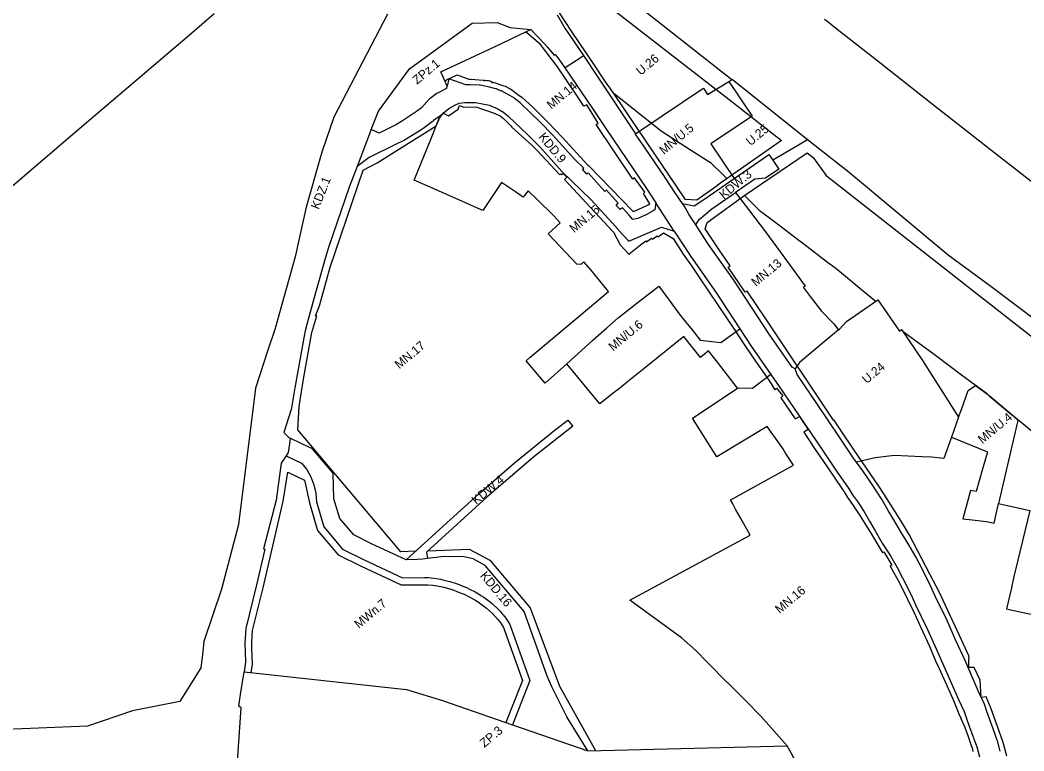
# Model space of a CAD drawing. Extents: x 7418616 to 7420822, y 5550745 to 5553106.
# Drawn here: x 7419553 to 7420122, y 5552455 to 5552869 of the extents above; entities that cross this region are included whole.
import ezdxf

# ---------------------------------------------------------------- set-up
doc = ezdxf.new("R2010")
doc.units = 0
for name, color, linetype in [('granica obszaru objętego planem', 7, 'Continuous'), ('granica strefy zwiększonej wysokości zabudowy', 7, 'Continuous'), ('linie rozgraniczające', 7, 'Continuous'), ('nieprzekraczalne linie zabudowy', 7, 'Continuous'), ('przeznaczenia terenów', 7, 'Continuous')]:
    doc.layers.add(name, color=color, linetype=linetype)

msp = doc.modelspace()

# ---------------------------------------------------------------- linework, layer by layer
at = {"layer": 'granica obszaru objętego planem'}
for points in [[(7419511.19, 5552742.76), (7419587.29, 5552807.63), (7419649.27, 5552860.47), (7419663.39, 5552872.55)], [(7420009.05, 5552869.32), (7420011.09, 5552867.73), (7420013.23, 5552866.06), (7420016.26, 5552863.7), (7420037.45, 5552847.04), (7420069.08, 5552822.2), (7420100.3, 5552797.65), (7420126.01, 5552777.58)]]:
    msp.add_lwpolyline(points, dxfattribs=at)
at = {"layer": 'granica strefy zwiększonej wysokości zabudowy'}
for points in [[(7419953.76, 5552779.05), (7419951.41, 5552781.34), (7419945.01, 5552787.57), (7419933.17, 5552795.21), (7419916.46, 5552805.97), (7419900.76, 5552818.37), (7419889.84, 5552826.97)], [(7420037.9, 5552709.57), (7420037.54, 5552709.87), (7420030.83, 5552715.39), (7420028.98, 5552716.91), (7420025.2, 5552720.02), (7420015.41, 5552728.06), (7420010.79, 5552731.63), (7419996.62, 5552742.4), (7419993.7, 5552744.61), (7419983.14, 5552752.63), (7419975.57, 5552758.38), (7419972.82, 5552760.47), (7419966.67, 5552766.47), (7419963.6, 5552769.46), (7419963.6, 5552769.46)], [(7420128.4, 5552634.31), (7420121.47, 5552639.97), (7420116.2, 5552644.3), (7420115.06, 5552645.24), (7420102.17, 5552656.1), (7420101.24, 5552656.92), (7420100.49, 5552657.47), (7420096.92, 5552660.13), (7420087.43, 5552667.21), (7420071.86, 5552678.81), (7420059.99, 5552687.55), (7420054.92, 5552691.27), (7420053.6, 5552692.24)]]:
    msp.add_lwpolyline(points, dxfattribs=at)
at = {"layer": 'linie rozgraniczające'}
for p, q in [((7419956.54, 5552835), (7419872.88, 5552900.79)), ((7419954.88, 5552833.99), (7419956.54, 5552835)), ((7419752.34, 5552806.9), (7419744.23, 5552785.82)), ((7419923.94, 5552749.19), (7419913.47, 5552765.28)), ((7420084.95, 5552643.93), (7420080.88, 5552632.69)), ((7420107.63, 5552595.09), (7420125.31, 5552591.19)), ((7419832.38, 5552469.77), (7419874.87, 5552455.06)), ((7419874.87, 5552455.06), (7419987.78, 5552457.79))]:
    msp.add_line(p, q, dxfattribs=at)
for points in [[(7419511.19, 5552742.76), (7419587.29, 5552807.63), (7419649.27, 5552860.47), (7419663.39, 5552872.55)], [(7419761.46, 5552872.12), (7419731.19, 5552813.82), (7419724.58, 5552794.59), (7419723.5, 5552791.44), (7419715.5, 5552762.81), (7419712.67, 5552750.3), (7419709.62, 5552736.46), (7419709.14, 5552734.73), (7419698.05, 5552694.95), (7419697.83, 5552694.15), (7419693.59, 5552681.37), (7419686.69, 5552660.34), (7419677.11, 5552583.24), (7419667.39, 5552546.6), (7419657.52, 5552516.96), (7419656.86, 5552511.21), (7419655.81, 5552502.07), (7419643.8, 5552483.02), (7419617.1, 5552477.61), (7419591.51, 5552469.04), (7419508.13, 5552465.61)], [(7419752.34, 5552806.9), (7419756.31, 5552817.21), (7419773.92, 5552841.15), (7419809.49, 5552867.01), (7419823.66, 5552867.37), (7419831.02, 5552864.55), (7419842.51, 5552863.51), (7419842.62, 5552863.41)], [(7419857.66, 5552871.76), (7419861.98, 5552864.31), (7419872.48, 5552848.66)], [(7420009.05, 5552869.32), (7420011.09, 5552867.73), (7420013.23, 5552866.06), (7420016.26, 5552863.7), (7420037.45, 5552847.04), (7420069.08, 5552822.2), (7420100.3, 5552797.65), (7420126.01, 5552777.58)], [(7419795.2, 5552831.44), (7419793.94, 5552834.32), (7419791.76, 5552839.51), (7419822.43, 5552853.79), (7419840.21, 5552862.41), (7419842.62, 5552863.41)], [(7419842.62, 5552863.41), (7419843.74, 5552862.28), (7419845.58, 5552860.39), (7419846.51, 5552859.44), (7419850.32, 5552855.63), (7419850.51, 5552855.38), (7419851.85, 5552853.63), (7419855.85, 5552848.96), (7419856.43, 5552849.35), (7419858.53, 5552846.61), (7419861.9, 5552841.73)], [(7419861.9, 5552841.73), (7419862.14, 5552841.89), (7419871.71, 5552848.2), (7419872.48, 5552848.66)], [(7419872.48, 5552848.66), (7419880.27, 5552837.04), (7419902.02, 5552804.48)], [(7419861.9, 5552841.73), (7419877.6, 5552818.69), (7419885.52, 5552806.89), (7419908.16, 5552773.44), (7419913.47, 5552765.28)], [(7419913.47, 5552765.28), (7419912.82, 5552761.39), (7419911.94, 5552760.8), (7419907.55, 5552758.32), (7419907.47, 5552758.32), (7419903.34, 5552756.4), (7419900.37, 5552755.91), (7419899.25, 5552757.18), (7419898.31, 5552758.38), (7419894.65, 5552762.4), (7419893.18, 5552761.51), (7419891, 5552763.9), (7419892.21, 5552765.08), (7419885.49, 5552772.46), (7419884.56, 5552771.74), (7419875.1, 5552782.25), (7419874.43, 5552781.61), (7419871.98, 5552784.45), (7419872.67, 5552785.04), (7419867.6, 5552789.93), (7419855.21, 5552803.56), (7419847.93, 5552810.98), (7419836.74, 5552821.75), (7419836.57, 5552821.91), (7419833.28, 5552824.64), (7419832.87, 5552824.94), (7419832.56, 5552825.13), (7419828.41, 5552827.48), (7419828, 5552827.69), (7419827.27, 5552828.02), (7419826.32, 5552828.9), (7419825.94, 5552828.62), (7419823.58, 5552829.68), (7419823.27, 5552829.8), (7419822.93, 5552829.9), (7419818.44, 5552831.08), (7419813.89, 5552831.96), (7419813.56, 5552831.99), (7419808.26, 5552832.21), (7419805.77, 5552832.21), (7419796.21, 5552835.55), (7419795.2, 5552831.44)], [(7419902.02, 5552804.48), (7419905.45, 5552806.79), (7419928.51, 5552822.26), (7419928.75, 5552822.42), (7419940.43, 5552830.25), (7419940.73, 5552829.82), (7419942.71, 5552826.63), (7419942.82, 5552826.74), (7419954.16, 5552833.56), (7419954.88, 5552833.99)], [(7419954.88, 5552833.99), (7419967.94, 5552814.48), (7419944.56, 5552798.82), (7419957.81, 5552779.08)], [(7419999.41, 5552800.99), (7419956.78, 5552835.14), (7419956.54, 5552835)], [(7419795.2, 5552831.44), (7419795.18, 5552831.35), (7419794.87, 5552830.07), (7419790.15, 5552827.65), (7419789.66, 5552827.36), (7419785.59, 5552824.4), (7419785.34, 5552824.19), (7419785.1, 5552823.97), (7419782.25, 5552820.9), (7419780.67, 5552819.08), (7419777.87, 5552817), (7419775.74, 5552815.45), (7419772.83, 5552813.6), (7419769.34, 5552811.35), (7419766.14, 5552809.42), (7419761.71, 5552807.24), (7419756.72, 5552804.83), (7419752.34, 5552806.9)], [(7419791.06, 5552814.47), (7419793.1, 5552816.02), (7419796.27, 5552818.73), (7419799.6, 5552820.66), (7419802.06, 5552821.75), (7419805.23, 5552822.21), (7419808.16, 5552822.21), (7419811.25, 5552822.08), (7419819.2, 5552820.54), (7419819.99, 5552820.33), (7419823.68, 5552818.67), (7419827.24, 5552816.65), (7419829.93, 5552814.42), (7419840.94, 5552803.82), (7419847.87, 5552796.76), (7419860.31, 5552783.08), (7419876.93, 5552767), (7419890.72, 5552751.86), (7419892.05, 5552750.14), (7419892.24, 5552749.92), (7419898.27, 5552743.61), (7419916.6, 5552751.5), (7419923.94, 5552749.19)], [(7419791.06, 5552814.47), (7419787.61, 5552811.86), (7419787.38, 5552811.63), (7419787.06, 5552811.38), (7419783.82, 5552808.96), (7419781.49, 5552807.27), (7419774.56, 5552802.81), (7419771.11, 5552800.74), (7419770.74, 5552800.54), (7419766.11, 5552798.26), (7419751.2, 5552791.07), (7419744.23, 5552785.82)], [(7419863.01, 5552674.16), (7419850.8, 5552663.17), (7419840.04, 5552675.92), (7419842.35, 5552677.85), (7419870.05, 5552701.17), (7419875.9, 5552706.11), (7419886.58, 5552715.12), (7419876.81, 5552727.26), (7419872.68, 5552731.87), (7419870.91, 5552730.48), (7419868.69, 5552730.64), (7419852.44, 5552747.72), (7419859.26, 5552754.09), (7419855.53, 5552758.1), (7419846.1, 5552767.33), (7419841.15, 5552772.14), (7419838.29, 5552768.62), (7419837.21, 5552769.35), (7419834.49, 5552771.18), (7419826.13, 5552776.8), (7419815.51, 5552761.02), (7419793.79, 5552770.54), (7419776.59, 5552778.12), (7419786.22, 5552801.72), (7419789.12, 5552808.86), (7419790.54, 5552812.34), (7419791.06, 5552814.47)], [(7419928.52, 5552764.94), (7419924.86, 5552770.37), (7419924.69, 5552770.63), (7419918.96, 5552779.21), (7419918.36, 5552780.14), (7419904.66, 5552800.36), (7419904.44, 5552800.69), (7419902.02, 5552804.28), (7419902.02, 5552804.48)], [(7419999.41, 5552800.99), (7419990.99, 5552796.02), (7419979.75, 5552789.39)], [(7420315.68, 5552545.3), (7420299.67, 5552559.37), (7420293.91, 5552563.84), (7420282.98, 5552572.32), (7420270.37, 5552582.11), (7420259.31, 5552590.7), (7420247.5, 5552599.87), (7420235.93, 5552609.17), (7420223.99, 5552618.12), (7420216.53, 5552623.99), (7420206.96, 5552631.81), (7420203.16, 5552634.99), (7420193.46, 5552643.91), (7420178, 5552656.63), (7420165.36, 5552667.99), (7420163.22, 5552670.42), (7420147.94, 5552682.92), (7420134.85, 5552693.95), (7420132.47, 5552696.06), (7420130.02, 5552697.81), (7420103.9, 5552717.31), (7420079.03, 5552735.61), (7420022.01, 5552783.22), (7419999.41, 5552800.99)], [(7419957.81, 5552779.08), (7419974.77, 5552790.76), (7419977.5, 5552792.64), (7419979.75, 5552789.39)], [(7419979.75, 5552789.39), (7419983.18, 5552784.41), (7419975.62, 5552779.2), (7419969.57, 5552778.72), (7419958.66, 5552771.19)], [(7419744.23, 5552785.82), (7419739.76, 5552774.21), (7419728.04, 5552739.95), (7419726.22, 5552733.76), (7419719.78, 5552710.9), (7419716.51, 5552699.28), (7419714.79, 5552692.81), (7419714.1, 5552688.94), (7419709.02, 5552660.49), (7419707.12, 5552649.25), (7419706.86, 5552648.4), (7419702.84, 5552635.34), (7419705.9, 5552632.31), (7419706.42, 5552632.06)], [(7419928.52, 5552764.94), (7419935.25, 5552763.53), (7419941.2, 5552767.63), (7419957.81, 5552779.08)], [(7419936.14, 5552752.8), (7419938.08, 5552755.8), (7419945.13, 5552761.86), (7419958.66, 5552771.19)], [(7419958.66, 5552771.19), (7419966.58, 5552760.75), (7419975.51, 5552748.98), (7419991.62, 5552727), (7419998.13, 5552718.13), (7419996.9, 5552717.53), (7420001.46, 5552711.58), (7420007.33, 5552703.93), (7420014.37, 5552696.89), (7420016.09, 5552694.4), (7420016.98, 5552693.33)], [(7419936.14, 5552752.8), (7419932.38, 5552758.58), (7419929.83, 5552762.99), (7419928.52, 5552764.94)], [(7419923.94, 5552749.19), (7419933.25, 5552734.9), (7419947.46, 5552714.74), (7419961.09, 5552694.01)], [(7419992.43, 5552671.38), (7419990.65, 5552672.19), (7419977.68, 5552691), (7419957.58, 5552721.57), (7419943.37, 5552741.71), (7419936.14, 5552752.8)], [(7419863.01, 5552674.16), (7419877.79, 5552687.48), (7419885.66, 5552694.56), (7419892.06, 5552700.2), (7419902.76, 5552708.58), (7419915.09, 5552718.22), (7419927.75, 5552700.99), (7419933.96, 5552693.33), (7419938.54, 5552687.59), (7419950.37, 5552686.24), (7419961.09, 5552694.01)], [(7420016.98, 5552693.33), (7420017.48, 5552693.75), (7420021.47, 5552698.11), (7420039.21, 5552710.48), (7420051.42, 5552692.74), (7420052.7, 5552693.59), (7420064.45, 5552676.07), (7420084.95, 5552643.93)], [(7419961.09, 5552694.01), (7419967.54, 5552684.2), (7419978.67, 5552668.07)], [(7420016.98, 5552693.33), (7419994.89, 5552674.84), (7419992.43, 5552671.38)], [(7419959.77, 5552660.36), (7419948.4, 5552675.1), (7419946.91, 5552677.02), (7419943.37, 5552681.55), (7419938.73, 5552677.75), (7419929.28, 5552689.57), (7419908.8, 5552673.1), (7419897.49, 5552664.02), (7419893.06, 5552660.44), (7419888.59, 5552656.92), (7419881.83, 5552651.6), (7419863.01, 5552674.16)], [(7419978.67, 5552668.07), (7419968.17, 5552660.25), (7419959.77, 5552660.36)], [(7419978.67, 5552668.07), (7419983.35, 5552661.28), (7419994.62, 5552644.77), (7420007.78, 5552625.23), (7420015.83, 5552613.36), (7420020.78, 5552606.41), (7420022.57, 5552603.78), (7420024.88, 5552600.05), (7420027.78, 5552596.15), (7420031.3, 5552590.69), (7420034.43, 5552585.06), (7420037.75, 5552579.6), (7420041.73, 5552572.72), (7420046.3, 5552565.36), (7420050.16, 5552558.88), (7420053.22, 5552553.06), (7420058.01, 5552543.28), (7420060.68, 5552537.4), (7420067.3, 5552523.74), (7420072.16, 5552512.75), (7420077.43, 5552501.27), (7420084.92, 5552484.07), (7420088.11, 5552477.33), (7420089.39, 5552473.33), (7420090.89, 5552469.04), (7420093.06, 5552463.31), (7420095.28, 5552457.36), (7420096.79, 5552451.59)], [(7420027.16, 5552618.48), (7420025.88, 5552620.27), (7420022.11, 5552625.82), (7420017.89, 5552632.06), (7420004.71, 5552651.63), (7419994.22, 5552667.01), (7419993.51, 5552668.17), (7419992.43, 5552671.38)], [(7419987.78, 5552457.79), (7419972.94, 5552474.73), (7419964.07, 5552483.75), (7419954.62, 5552493.15), (7419954.14, 5552493.62), (7419942.69, 5552505), (7419936.15, 5552511.87), (7419928.09, 5552519.09), (7419898.8, 5552540.39), (7419966.87, 5552577.11), (7419961.4, 5552586.93), (7419958.85, 5552591.49), (7419957.01, 5552594.81), (7419955.72, 5552597.1), (7419957.3, 5552597.97), (7419991.39, 5552616.81), (7419986.94, 5552623.65), (7419985.32, 5552626.15), (7419983.64, 5552628.59), (7419978.83, 5552635.39), (7419976.53, 5552638.64), (7419947.99, 5552621.51), (7419934.31, 5552643.35), (7419956.12, 5552657.93), (7419959.77, 5552660.36)], [(7420084.95, 5552643.93), (7420086.75, 5552648.87), (7420090.46, 5552658.99), (7420094.45, 5552661.97), (7420101.24, 5552656.92), (7420102.17, 5552656.1), (7420115.06, 5552645.24), (7420118.58, 5552642.35), (7420118.33, 5552641.26), (7420107.63, 5552595.09)], [(7419772.1, 5552563.1), (7419792.99, 5552582.19), (7419812.95, 5552600.39), (7419833.39, 5552618.02), (7419856.71, 5552636.92), (7419863.6, 5552642.35), (7419866.12, 5552639.25), (7419866.44, 5552638.86), (7419844.3, 5552621.43), (7419817.72, 5552598.68), (7419783.54, 5552567.47), (7419784.21, 5552563.89)], [(7419706.42, 5552632.06), (7419705.98, 5552628.96), (7419705.28, 5552623.98), (7419705.17, 5552623.93), (7419704.03, 5552622.13)], [(7419772.1, 5552563.1), (7419752.46, 5552572.28), (7419742.35, 5552577.31), (7419734.47, 5552586.66), (7419731.16, 5552597.73), (7419730.7, 5552612.31), (7419718.93, 5552626.12), (7419712.63, 5552629.12), (7419706.42, 5552632.06)], [(7420080.88, 5552632.69), (7420076.5, 5552620.58), (7420069.55, 5552621.33), (7420064.05, 5552621.58), (7420048.73, 5552622.26), (7420037.72, 5552620.97), (7420027.16, 5552618.48)], [(7420080.88, 5552632.69), (7420101.29, 5552624.4), (7420101.13, 5552623.66), (7420098.37, 5552614.01), (7420094.92, 5552601.8), (7420091.78, 5552602.48), (7420087.38, 5552586.39), (7420092.68, 5552585.79), (7420100.71, 5552584.84), (7420105.04, 5552583.87), (7420107.63, 5552595.09)], [(7419704.03, 5552622.13), (7419701.36, 5552617.89), (7419698.38, 5552597.06), (7419691.29, 5552569.33), (7419691.97, 5552569.14), (7419687.37, 5552549.04), (7419681.18, 5552524.32), (7419680.61, 5552516.08), (7419681.02, 5552505.46), (7419680.88, 5552503.76), (7419680.25, 5552499.71)], [(7419704.03, 5552622.13), (7419712.7, 5552618.01), (7419715.72, 5552614.26), (7419718.13, 5552610.1), (7419719.87, 5552605.61), (7419720.9, 5552600.91), (7419721.21, 5552596.11), (7419725.48, 5552581.8), (7419736.04, 5552569.28), (7419748.36, 5552563.16), (7419770.06, 5552553.02), (7419782.5, 5552553.22), (7419784.7, 5552553.12), (7419786.2, 5552552.93), (7419787.7, 5552552.82), (7419789.12, 5552552.63), (7419790.31, 5552552.38), (7419791.54, 5552552.17), (7419792.83, 5552551.89), (7419794.29, 5552551.55), (7419795.81, 5552551.15), (7419796.91, 5552550.9), (7419797.99, 5552550.54), (7419799.43, 5552550.13), (7419801.04, 5552549.56), (7419802.05, 5552549.14), (7419804.11, 5552548.36), (7419805.38, 5552547.83), (7419806.58, 5552547.3), (7419808, 5552546.64), (7419811.09, 5552545.03), (7419813.06, 5552543.89), (7419814.41, 5552543.03), (7419816, 5552541.97), (7419817.63, 5552540.83), (7419819.09, 5552539.73), (7419820.75, 5552538.41), (7419821.89, 5552537.4), (7419823.71, 5552535.69), (7419824.73, 5552534.69), (7419825.49, 5552533.85), (7419826.32, 5552532.87), (7419827.08, 5552531.96), (7419828.54, 5552530.16), (7419829.92, 5552528.09), (7419830.8, 5552526.65), (7419842.15, 5552494.83), (7419832.38, 5552469.77)], [(7420108.57, 5552454.77), (7420107, 5552460.77), (7420106.87, 5552461.16), (7420104.48, 5552467.59), (7420102.39, 5552473.14), (7420100.95, 5552477.23), (7420099.6, 5552481.44), (7420099.43, 5552481.91), (7420096.07, 5552489.03), (7420088.59, 5552506.2), (7420083.27, 5552517.8), (7420078.42, 5552528.77), (7420071.69, 5552542.65), (7420069.08, 5552548.41), (7420064.13, 5552558.51), (7420060.77, 5552564.91), (7420056.7, 5552571.75), (7420052.14, 5552579.08), (7420048.21, 5552585.88), (7420044.99, 5552591.18), (7420041.87, 5552596.79), (7420041.66, 5552597.13), (7420035.26, 5552607.06), (7420030.62, 5552613.64), (7420027.16, 5552618.48)], [(7420125.31, 5552591.19), (7420118.51, 5552562.92), (7420116.31, 5552553.71), (7420114.85, 5552547.43), (7420112.01, 5552535.5), (7420116.32, 5552534.47), (7420123.3, 5552532.97), (7420130.59, 5552531.52), (7420140.63, 5552529.23), (7420148.9, 5552527.33)], [(7419784.21, 5552563.89), (7419781.46, 5552563.52), (7419778.26, 5552563.32), (7419772.1, 5552563.1)], [(7419874.87, 5552455.06), (7419863.09, 5552474.37), (7419858.95, 5552482.52), (7419854.66, 5552491.19), (7419851.86, 5552497.38), (7419838.84, 5552533.89), (7419816.86, 5552559.9), (7419809.96, 5552563.74), (7419804, 5552565.02), (7419791.88, 5552564.91), (7419784.21, 5552563.89)], [(7419676.51, 5552449.1), (7419678.57, 5552479.45), (7419677.27, 5552480.3), (7419678.28, 5552486.89), (7419680.25, 5552499.71)], [(7419680.25, 5552499.71), (7419772.19, 5552489.86), (7419792.7, 5552483.51), (7419832.38, 5552469.77)], [(7419998.25, 5552439.19), (7419998.18, 5552439.22), (7419987.78, 5552457.79)]]:
    msp.add_lwpolyline(points, dxfattribs=at)
at = {"layer": 'nieprzekraczalne linie zabudowy'}
for points in [[(7419854.22, 5552880.23), (7419862.41, 5552895.83), (7419956.75, 5552822.57), (7419984.73, 5552800.63), (7419948.25, 5552775.21), (7419948.2, 5552774.88), (7419936.75, 5552766.9), (7419930.27, 5552767.21), (7419890.06, 5552826.64), (7419887.27, 5552830.75), (7419886.32, 5552832), (7419884.57, 5552834.42), (7419884.67, 5552834.49), (7419877.92, 5552844.35), (7419866.03, 5552861.89), (7419854.22, 5552880.23)], [(7419793.97, 5552834.25), (7419794.93, 5552835.02), (7419800.97, 5552837.85), (7419807.65, 5552835.27), (7419808.04, 5552835.28), (7419808.22, 5552835.27), (7419808.24, 5552835.24), (7419808.29, 5552835.27), (7419808.44, 5552835.27), (7419815.95, 5552834.76), (7419816.23, 5552834.33), (7419816.82, 5552834.71), (7419818, 5552834.63), (7419818.64, 5552834.55), (7419819.55, 5552834.31), (7419820.29, 5552834.06), (7419820.8, 5552833.28), (7419821.42, 5552833.67), (7419827.32, 5552831.65), (7419828.1, 5552831.31), (7419831.34, 5552829.61), (7419831.86, 5552829.27), (7419835.36, 5552826.73), (7419837.8, 5552824.91), (7419843.58, 5552819.74), (7419852.17, 5552811.15), (7419852.55, 5552810.79), (7419860.47, 5552802.41), (7419874.95, 5552786.74), (7419875.48, 5552786.21), (7419900.38, 5552760.59), (7419900.72, 5552760.4), (7419901.84, 5552760.87), (7419905.95, 5552762.72), (7419909.18, 5552764.25), (7419910, 5552764.74), (7419906.47, 5552770.64), (7419907.17, 5552771.33), (7419901.48, 5552779.45), (7419900.54, 5552778.77), (7419879.74, 5552809.69), (7419880.73, 5552810.45), (7419874.31, 5552820.8), (7419872.75, 5552820.07), (7419869.79, 5552824.46), (7419869.41, 5552825), (7419861.81, 5552836.49), (7419857.69, 5552842.32), (7419848.06, 5552855.02), (7419840.39, 5552861.66), (7419838.94, 5552861.79)], [(7419777.47, 5552568.01), (7419769.08, 5552567.69), (7419710.71, 5552636.79), (7419711.49, 5552650.06), (7419713.96, 5552665.4), (7419718.69, 5552691.92), (7419721.46, 5552701.33), (7419720.65, 5552701.42), (7419722.9, 5552706.99), (7419729.01, 5552728.91), (7419747.81, 5552783.89), (7419755.62, 5552787.88), (7419789.15, 5552808.91), (7419790.63, 5552812.71), (7419793.1, 5552816.02), (7419796.13, 5552814.54), (7419801.57, 5552818.45), (7419802.33, 5552820.35), (7419804.67, 5552819.41), (7419804.89, 5552819.48), (7419811.46, 5552819.69), (7419821.92, 5552816.05), (7419825.4, 5552814.5), (7419827.26, 5552813.12), (7419831.28, 5552808.83), (7419831.87, 5552808.23), (7419843.42, 5552797.84), (7419846.26, 5552795.02), (7419859.15, 5552781.21), (7419859.63, 5552781.73), (7419860.28, 5552781.13), (7419860.99, 5552781.87), (7419863.09, 5552779.77), (7419861.73, 5552778.44), (7419889.06, 5552749.15), (7419889.53, 5552748.69), (7419893.33, 5552741.55), (7419898.25, 5552736.27), (7419904.72, 5552741.52), (7419907.82, 5552743.72), (7419908.16, 5552743.24), (7419911.05, 5552745.26), (7419911.52, 5552744.68), (7419914.32, 5552746.68), (7419914.74, 5552746.09), (7419917.83, 5552748.29), (7419923.29, 5552745.22), (7419929, 5552736.28), (7419930.92, 5552733.58), (7419933.64, 5552729.67), (7419938.12, 5552722.9), (7419953.46, 5552700.14), (7419958.21, 5552693.14), (7419962.31, 5552686.81), (7419968.16, 5552678.1), (7419977.76, 5552664.3), (7419980.94, 5552659.5), (7419981.86, 5552660.41), (7419985.33, 5552656.05), (7419984.2, 5552654.84), (7419992.3, 5552642.95), (7419994.88, 5552644.38), (7419999.84, 5552637.02), (7419997.29, 5552635.51), (7420003.42, 5552626.26), (7420010.07, 5552616.39), (7420019.15, 5552602.96), (7420019.75, 5552602.29), (7420019.67, 5552602.24), (7420019.85, 5552601.99), (7420020.08, 5552601.74), (7420022.12, 5552598.46), (7420024.87, 5552594.51), (7420029, 5552588.35), (7420036.25, 5552576.75), (7420041.66, 5552567.61), (7420041.85, 5552567.25), (7420042.52, 5552567.65), (7420047.06, 5552560.13), (7420046.2, 5552559.62), (7420051.71, 5552549.84), (7420060.17, 5552532.35), (7420063.52, 5552524.97), (7420068.25, 5552514.61), (7420071.96, 5552506.01), (7420073.94, 5552501.69), (7420081.63, 5552484.56), (7420085.43, 5552474.97), (7420086.31, 5552473.44), (7420086.14, 5552473.34), (7420088.22, 5552468.77), (7420090.13, 5552463.67), (7420092.08, 5552458.15), (7420092.55, 5552456.68), (7420093.03, 5552454.59)], [(7420112.21, 5552452.02), (7420110.18, 5552459.81), (7420110.04, 5552460.26), (7420107.07, 5552468.85), (7420103.41, 5552478.75), (7420100.6, 5552485.64), (7420097.82, 5552485.22), (7420097.11, 5552495.12), (7420093.79, 5552502.3), (7420090.78, 5552502.28), (7420090.75, 5552507.18), (7420090.85, 5552507.18), (7420090.79, 5552508.79), (7420085.44, 5552520.36), (7420076.24, 5552540.19), (7420074.07, 5552544.69), (7420068.7, 5552555), (7420056.89, 5552577.56), (7420052.4, 5552585.02), (7420044.28, 5552597.93), (7420040.16, 5552604.25), (7420025.49, 5552625.91), (7420018.48, 5552636.31), (7420014.3, 5552642.48), (7420014.11, 5552642.36), (7419997.07, 5552667.72), (7419997.17, 5552667.77), (7419992.84, 5552674.17), (7419990.91, 5552677.08), (7419975.72, 5552699.59), (7419965.17, 5552715.27), (7419964.06, 5552714.79), (7419954.42, 5552728.84), (7419955.5, 5552729.58), (7419949.29, 5552738.77), (7419941.41, 5552750.53), (7419942.49, 5552754.26), (7419963.23, 5552769.21), (7419999.26, 5552793.59), (7420002.64, 5552790.94), (7420009.96, 5552780.85), (7420097.4, 5552712.29), (7420192.63, 5552637.79)], [(7419684.23, 5552499.28), (7419684.99, 5552504.2), (7419684.72, 5552513.17), (7419684.66, 5552516.64), (7419685.12, 5552523.26), (7419686.53, 5552529.2), (7419691.07, 5552547.34), (7419702.32, 5552596.33), (7419704.98, 5552612.77), (7419714.51, 5552608.36), (7419717.24, 5552595.41), (7419721.89, 5552579.86), (7419733.52, 5552566.07), (7419746.63, 5552559.55), (7419769.24, 5552548.98), (7419770.5, 5552548.98), (7419784.52, 5552549.12), (7419787.17, 5552548.85), (7419790.76, 5552548.24), (7419793.32, 5552547.67), (7419798.19, 5552546.33), (7419801.8, 5552544.97), (7419803.82, 5552544.14), (7419804.9, 5552543.67), (7419807.69, 5552542.29), (7419811, 5552540.46), (7419813.05, 5552539.13), (7419817.59, 5552535.81), (7419820.89, 5552532.85), (7419824.04, 5552529.36), (7419825.3, 5552527.81), (7419827.19, 5552524.87), (7419837.88, 5552494.9), (7419828.6, 5552471.08)], [(7419784.43, 5552568.28), (7419807.84, 5552569.2), (7419819.44, 5552563.04), (7419842.35, 5552535.94), (7419858.97, 5552491.67), (7419879.37, 5552455.17)]]:
    msp.add_lwpolyline(points, dxfattribs=at)

# ---------------------------------------------------------------- texts
at = {"layer": 'przeznaczenia terenów'}
for s, rotation, p in [('U.26', 39.8439, (7419904.9, 5552837.18)), ('ZPz.1', 39.8439, (7419778.27, 5552832.16)), ('MN.14', 39.8439, (7419854.28, 5552818.02)), ('MN/U.5', 39.8439, (7419918.05, 5552792.38)), ('U.25', 39.8439, (7419967.13, 5552797.31)), ('KDD.9', 309.8439, (7419846.75, 5552802.48)), ('KDW.3', 39.8439, (7419951.98, 5552767.08)), ('KDZ.1', 68.2847, (7419722.55, 5552761.25)), ('MN.15', 39.8439, (7419867.13, 5552748.12)), ('MN.13', 39.8439, (7419970.12, 5552717.69)), ('MN/U.6', 39.8439, (7419889.24, 5552681.1)), ('MN.17', 39.8439, (7419768.17, 5552671.04)), ('U.24', 39.8439, (7420032.86, 5552662.62)), ('MN/U.4', 39.8439, (7420098.43, 5552628.62)), ('KDW.4', 39.8439, (7419811.8, 5552594.17)), ('KDD.16', 309.8439, (7419813.61, 5552554.05)), ('MN.16', 39.8439, (7419983.61, 5552532.45)), ('MWn.7', 39.8439, (7419745.26, 5552524.08)), ('ZP.3', 39.8439, (7419816.37, 5552456.68))]:
    msp.add_text(s, height=5, rotation=rotation, dxfattribs=at).set_placement(p)

doc.saveas('drawing.dxf')
